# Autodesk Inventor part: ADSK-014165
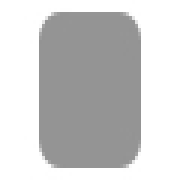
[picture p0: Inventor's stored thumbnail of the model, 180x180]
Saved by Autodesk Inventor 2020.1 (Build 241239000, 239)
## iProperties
Created: 2019-01
Part Number: ADSK-014165
Material: Stahl, weich
Document SubType Name: Modeling
Designer: lutzd
Language: de-DE
Size Designation: 5 x 60 x 40
Categories: <MemberInstance><Categories><Category DisplayName="Sonstige Bauteile" InternalName="5aa15e00-363f-49f2-933f-16f664388e3f" Mnemonic="OTHER"><Category DisplayName
Mass: 93.3577 g
Surface Area: 57.1416 cm^2
Volume: 11.8927 cm^3
Density: 7.85 g/cm^3
Appearance: Halbpoliert
IsCustomPart: 1
Title: end cap
Author: lutzd
Revision Number: -
Dimensions: 40x60x5 mm
Mass: 0,093 kg
DocNumber: ADSK-014165
Folder: 01 - Themengebiete\Simplification\01 - Packaging machine\
VDS_Category: 3D Komponenten
VDS_NumSchm: Autodesk
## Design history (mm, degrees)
sketch "Sketch1"
  geometry: L1 (0, 20.175)-(0, -21.446); L2 (-20.203, 0)-(20.169, 0); L3 (-20, 30)-(20, 30); L4 (20, 30)-(20, -30); L5 (20, -30)-(-20, -30); L6 (-20, -30)-(-20, 30); 1 further point
  constraints: 12 end point, 2 horizontal, 2 parallel, 2 point on line, 1 perpendicular, 1 vertical
  dimensions: "d0" = 60 distance between parallel lines of L5 L3 (= height); "d1" = 30 distance between parallel lines of L2 L3 (= 0.5 x height); "d2" = 40 distance between parallel lines of L6 L4 (= width); "d3" = 20 distance between parallel lines of L6 L1 (= 0.5 x width)
extrude "Extrusion1" new body sketch "Sketch1" distance "d4" = 5 (= thickness); taper "d5" = 0 deg
fillet "Fillet1" dims "d6" = 5 (= fillet), "d7" = 0, "fillet" = 5 [user parameter; used in 1 equation term]
chamfer "Chamfer1" distance "d8" = 0 (computed from chamfer); stored, may be unused: second distance "d9" = 2, angle "d10" = 45 deg; dims "d11" = 0, "chamfer" = 0 [user parameter; used in 1 equation term]
body "Solid1"
other parameters: "thickness" = 5 [user parameter; used in 1 equation term], "width" = 40 [user parameter; used in 2 equation terms], "height" = 60 [user parameter; used in 2 equation terms]
